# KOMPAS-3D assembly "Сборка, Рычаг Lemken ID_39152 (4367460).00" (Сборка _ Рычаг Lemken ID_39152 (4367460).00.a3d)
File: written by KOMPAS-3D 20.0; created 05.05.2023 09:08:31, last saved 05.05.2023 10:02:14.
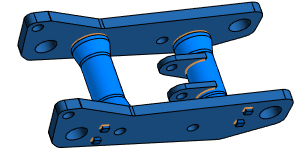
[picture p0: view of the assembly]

Document properties: Автор: factory; Полное имя файла: C:\Users\factory\Desktop\Чертежи\Рычаг Lemken ID_39152 (4367460)\Сборка _ Рычаг Lemken ID_39152 (4367460).00.a3d

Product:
- Part/product: Сборка  | designation Рычаг Lemken ID_39152 (4367460).00
    Масса: 65.0672
    source file: Сборка _ Рычаг Lemken ID_39152 (4367460).00_Чертёж.cdw
  - unknown [Обозначение сварного шва]: (unnamed)
      additional columns: 0; 1; 1; 0.016; 0.016; 0.00123308; 1; Длина, сечение шва и плотность наплавленного материала
  - unknown [Обозначение сварного шва]: (unnamed)
      additional columns: 0; 1; 1; 0.108888; 0.108888; 0.00839172; 1; Длина, сечение шва и плотность наплавленного материала
  - unknown [Обозначение сварного шва]: (unnamed)
      additional columns: 0; 1; 1; 0.054; 0.054; 0.00416163; 1; Длина, сечение шва и плотность наплавленного материала
  - unknown [Обозначение сварного шва]: (unnamed)
      additional columns: 0; 1; 1; 0.305932; 0.305932; 0.0235773; 1; Длина, сечение шва и плотность наплавленного материала
  - Component [detail]: Упор  | designation Рычаг Lemken ID_39152 (4367460).03  | qty 4  | pos. 3  | Материал: Лист$d10х700х5000 ГОСТ 19903-2015;295-09Г2 ГОСТ 19281-2014$ (density 7850 kg/m3); Масса: 0.02669; Форматы листов документа: A4; source file: Упор _ Рычаг Lemken ID_39152 (4367460).03.m3d, Упор _ Рычаг Lemken ID_39152 (4367460).03_Чертёж.cdw
  - Component [detail]: Ухо  | designation Рычаг Lemken ID_39152 (4367460).02  | qty 2  | pos. 2  | Материал: Лист$d16х1400х6000 ГОСТ 19903-2015;295-09Г2-ГС ГОСТ 19281-2014$ (density 7850 kg/m3); Масса: 0.803282; Форматы листов документа: A3; source file: Ухо _ Рычаг Lemken ID_39152 (4367460).02.m3d, Ухо _ Рычаг Lemken ID_39152 (4367460).02_Чертёж.cdw
  - Component [detail]: Втулка  | designation Рычаг Lemken ID_39152 (4367460).01  | qty 2  | pos. 1  | Материал: Сталь 40Х  ГОСТ 4543-2016 (density 7850 kg/m3); Масса: 8.48662; Комментарий: Модуль генерации 3D-моделей программы <Валы и механические передачи 2D>; source file: Втулка _ Рычаг Lemken ID_39152 (4367460).01.m3d
  - Component [detail]: Боковой кронштейн  | designation Рычаг Lemken ID_39152 (4367460).04  | qty 2  | pos. 4  | Материал: Лист$d32х1700х4200 ГОСТ 19903-2015;295-09Г2-ГС ГОСТ 19281-2014$ (density 7850 kg/m3); Масса: 23.1903; Форматы листов документа: A3; source file: Боковой кронштейн _ Рычаг Lemken ID_39152 (4367460).04.m3d, Боковой кронштейн _ Рычаг Lemken ID_39152 (4367460).04_Чертёж.cdw

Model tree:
1. Введите текст обозначения...  (with: Фаска:2, Элемент выдавливания:1, Фаска:4)  (labels: {F8D7F836-C962-4DAC-9A52-ED5B9D430847}; {B79062AB-18CA-4C2C-A874-8D817D118EDE}; OBJ2D_HIDDEN; {B8F93724-DA15-4186-B3D0-1CAD93540E6C})
     Длина линии сварного шва = 305.932; Длина сварного шва = 305.932; Масса* наплавленного материала = 0.0235773; Длина линии сварного шва = 305.932; Длина сварного шва = 305.932; Масса* наплавленного материала = 0.0235773; Длина линии сварного шва = 108.888; Длина сварного шва = 108.888; Масса* наплавленного материала = 0.00839172; Длина линии сварного шва = 108.888; Длина сварного шва = 108.888; Масса* наплавленного материала = 0.00839172; Длина линии сварного шва = 108.888; Длина сварного шва = 108.888; Масса* наплавленного материала = 0.00839172; Длина линии сварного шва = 108.888; Длина сварного шва = 108.888; Масса* наплавленного материала = 0.00839172; Длина линии сварного шва = 305.932; Длина сварного шва = 305.932; Масса* наплавленного материала = 0.0235773; Длина линии сварного шва = 305.932; Длина сварного шва = 305.932; Масса* наплавленного материала = 0.0235773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

Referenced files in C:\Users\factory\Desktop\Чертежи\Рычаг Lemken ID_39152 (4367460)\: Боковой кронштейн _ Рычаг Lemken ID_39152 (4367460).04.m3d, Втулка _ Рычаг Lemken ID_39152 (4367460).01.m3d, Ухо _ Рычаг Lemken ID_39152 (4367460).02.m3d, Упор _ Рычаг Lemken ID_39152 (4367460).03.m3d
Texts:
  Welding3DConfiguration
  Рычаг Lemken ID_39152 (4367460).00
  Обозначения сварных швов
  Рычаг Lemken ID_39152 (4367460).04 Боковой кронштейн (1)
  Рычаг Lemken ID_39152 (4367460).01 Втулка (1)
  Рычаг Lemken ID_39152 (4367460).01 Втулка (2)
  Рычаг Lemken ID_39152 (4367460).02 Ухо (1)
  Рычаг Lemken ID_39152 (4367460).02 Ухо (2)
  Рычаг Lemken ID_39152 (4367460).03 Упор (1)
  Рычаг Lemken ID_39152 (4367460).03 Упор (2)
  Рычаг Lemken ID_39152 (4367460).03 Упор (3)
  Рычаг Lemken ID_39152 (4367460).03 Упор (4)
